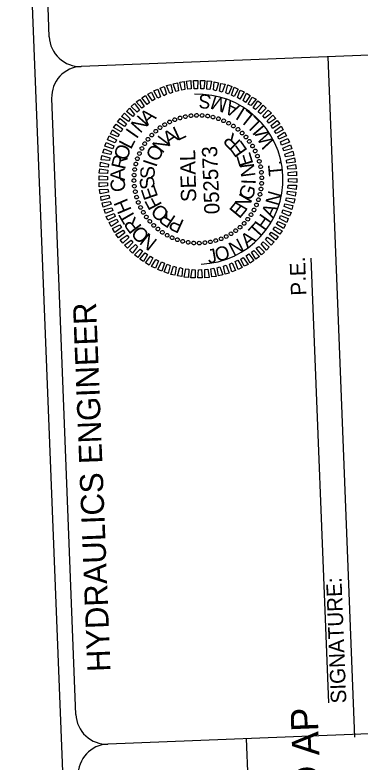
# Model space of a CAD drawing. Extents: x 1624323 to 1631382, y 753034 to 769560.
# Drawn here: x 1629687 to 1630364, y 765176 to 766642 of the extents above; entities that cross this region are included whole.
import ezdxf

# ---------------------------------------------------------------- set-up
doc = ezdxf.new("R2010")
doc.units = 0
for name, color, linetype in [('Old_Level_1', 7, 'Continuous'), ('Scratch_Level_0', 7, 'Continuous'), ('Sheet Data Field CELL', 7, 'Continuous'), ('Sheet Professional Seal CELL', 7, 'Continuous'), ('Sheet Profile Grid Minor CELL', 7, 'Continuous'), ('Sheet Title CELL', 7, 'Continuous')]:
    doc.layers.add(name, color=color, linetype=linetype)

msp = doc.modelspace()

# ---------------------------------------------------------------- linework, layer by layer
at = {"layer": 'Scratch_Level_0'}
msp.add_arc((1630045.7, 766319.7), 166.8, 272.2582, 92.2582, dxfattribs=at)
at = {"layer": 'Sheet Professional Seal CELL'}
for p, q in [((1630000.1, 766436.7), (1630000.1, 766436.7)), ((1630010.4, 766440.1), (1630010.4, 766440.1)), ((1630021.3, 766442.5), (1630021.3, 766442.5)), ((1630032, 766444.5), (1630032, 766444.5)), ((1630043, 766445.1), (1630043, 766445.1)), ((1630054, 766444.8), (1630054, 766444.8)), ((1630064.8, 766443.5), (1630064.8, 766443.5)), ((1630075.4, 766441.7), (1630075.4, 766441.7)), ((1630086.1, 766438.6), (1630086.1, 766438.6)), ((1630096.2, 766434.5), (1630096.2, 766434.5)), ((1629971.4, 766420.8), (1629971.4, 766420.8)), ((1629980.7, 766426.9), (1629980.7, 766426.9)), ((1629990.2, 766432.3), (1629990.2, 766432.3)), ((1630106.2, 766429.9), (1630106.2, 766429.9)), ((1630115.4, 766424), (1630115.4, 766424)), ((1629955, 766406.4), (1629955, 766406.4)), ((1629962.9, 766414.2), (1629962.9, 766414.2)), ((1630124.4, 766417.6), (1630124.4, 766417.6)), ((1630132.4, 766410.4), (1630132.4, 766410.4)), ((1629947.8, 766398.4), (1629947.8, 766398.4)), ((1630140.3, 766402.4), (1630140.3, 766402.4)), ((1630146.9, 766394), (1630146.9, 766394)), ((1629935.5, 766380.1), (1629935.5, 766380.1)), ((1629941.4, 766389.4), (1629941.4, 766389.4)), ((1630153, 766384.7), (1630153, 766384.7)), ((1630158.4, 766375.1), (1630158.4, 766375.1)), ((1629930.9, 766370.2), (1629930.9, 766370.2)), ((1630162.8, 766365.3), (1630162.8, 766365.3)), ((1629923.7, 766349.4), (1629923.7, 766349.4)), ((1629926.8, 766360), (1629926.8, 766360)), ((1630166.2, 766354.9), (1630166.2, 766354.9)), ((1629921.9, 766338.8), (1629921.9, 766338.8)), ((1630168.6, 766344), (1630168.6, 766344)), ((1630170.5, 766333.3), (1630170.5, 766333.3)), ((1629920.2, 766317), (1629920.2, 766317)), ((1629920.5, 766328), (1629920.5, 766328)), ((1630045.7, 766319.7), (1630045.7, 766319.7)), ((1630171.2, 766322.4), (1630171.2, 766322.4)), ((1629920.9, 766306), (1629920.9, 766306)), ((1630170.9, 766311.3), (1630170.9, 766311.3)), ((1629922.8, 766295.3), (1629922.8, 766295.3)), ((1630167.7, 766289.9), (1630167.7, 766289.9)), ((1630169.6, 766300.5), (1630169.6, 766300.5)), ((1629925.3, 766284.4), (1629925.3, 766284.4)), ((1629928.7, 766274), (1629928.7, 766274)), ((1630164.6, 766279.3), (1630164.6, 766279.3)), ((1629933.1, 766264.2), (1629933.1, 766264.2)), ((1630155.9, 766259.2), (1630155.9, 766259.2)), ((1630160.5, 766269.1), (1630160.5, 766269.1)), ((1629938.4, 766254.6), (1629938.4, 766254.6)), ((1629944.6, 766245.4), (1629944.6, 766245.4)), ((1630150, 766250), (1630150, 766250)), ((1629951.1, 766236.9), (1629951.1, 766236.9)), ((1629959, 766228.9), (1629959, 766228.9)), ((1630136.4, 766232.9), (1630136.4, 766232.9)), ((1630143.6, 766241), (1630143.6, 766241)), ((1629967, 766221.7), (1629967, 766221.7)), ((1629976, 766215.3), (1629976, 766215.3)), ((1630120, 766218.5), (1630120, 766218.5)), ((1630128.5, 766225.1), (1630128.5, 766225.1)), ((1629985.3, 766209.4), (1629985.3, 766209.4)), ((1629995.2, 766204.8), (1629995.2, 766204.8)), ((1630005.4, 766200.7), (1630005.4, 766200.7)), ((1630081, 766199.2), (1630081, 766199.2)), ((1630091.4, 766202.6), (1630091.4, 766202.6)), ((1630101.2, 766207), (1630101.2, 766207)), ((1630110.7, 766212.4), (1630110.7, 766212.4)), ((1630016, 766197.6), (1630016, 766197.6)), ((1630026.6, 766195.8), (1630026.6, 766195.8)), ((1630037.4, 766194.5), (1630037.4, 766194.5)), ((1630048.4, 766194.2), (1630048.4, 766194.2)), ((1630059.4, 766194.8), (1630059.4, 766194.8)), ((1630070.1, 766196.8), (1630070.1, 766196.8))]:
    msp.add_line(p, q, dxfattribs=at)
for points in [[(1630002.4, 766491.6), (1629997, 766507.1), (1630005.5, 766509), (1630007.6, 766493.3)], [(1630014.3, 766494.3), (1630010.2, 766510.4), (1630018.6, 766511.5), (1630020.3, 766495.5)], [(1630026.2, 766496.3), (1630023.6, 766512.4), (1630032.1, 766513.3), (1630032.2, 766497)], [(1630038.7, 766497), (1630037.3, 766513.2), (1630045.8, 766513.6), (1630044.7, 766497.3)], [(1630051.2, 766497.3), (1630051.1, 766513.5), (1630059.3, 766513.3), (1630057.2, 766497)], [(1630063.3, 766496.5), (1630064.1, 766512.5), (1630072.7, 766511.9), (1630069.3, 766495.5)], [(1630076.1, 766495), (1630077.5, 766510.6), (1630086, 766509.1), (1630081.4, 766493.2)], [(1630088.2, 766492.2), (1630090.8, 766507.8), (1630099.1, 766506.4), (1630093.5, 766490.4)], [(1629967.1, 766478.7), (1629959.1, 766493.1), (1629966.9, 766496.7), (1629972.5, 766481.4)], [(1629978.7, 766483.6), (1629971.6, 766498.6), (1629979.2, 766501.7), (1629983.8, 766486.3)], [(1629990.5, 766488.1), (1629984.2, 766503.9), (1629992.3, 766505.7), (1629995.7, 766490.1)], [(1630100.3, 766488.9), (1630104.2, 766504.6), (1630112.1, 766501.7), (1630105.7, 766486.4)], [(1630111.5, 766484.4), (1630116.7, 766500.1), (1630124.5, 766496.7), (1630117.1, 766482.1)], [(1630123.2, 766479.8), (1630128.9, 766494.3), (1630136.8, 766490.9), (1630128.1, 766477)], [(1629945.9, 766466.3), (1629935.8, 766479.2), (1629943.1, 766484.2), (1629950.7, 766470)], [(1629956.6, 766473.3), (1629947.3, 766486.9), (1629954.9, 766490.5), (1629961.2, 766476.5)], [(1630134.2, 766474.3), (1630141.1, 766488.5), (1630148.3, 766483.8), (1630138.8, 766470.4)], [(1630144.5, 766467.2), (1630152.4, 766481), (1630159.9, 766476.5), (1630149.3, 766464.1)], [(1629926.4, 766451.6), (1629914.7, 766462.6), (1629921.3, 766468.1), (1629931.3, 766455.3)], [(1629935.9, 766459.4), (1629924.9, 766471.3), (1629931.9, 766476.3), (1629940.5, 766462.6)], [(1630154.3, 766460), (1630163.5, 766473.4), (1630170.2, 766468.2), (1630158.9, 766456.7)], [(1630164.1, 766451.7), (1630173.8, 766464.8), (1630179.8, 766458.8), (1630168.3, 766447.8)], [(1629909.4, 766433.1), (1629896, 766442.9), (1629901.7, 766449.1), (1629912.9, 766438)], [(1629917.8, 766442.5), (1629905.6, 766452.7), (1629911.4, 766459), (1629921.6, 766446.4)], [(1630173.2, 766443.8), (1630183.7, 766455.2), (1630190, 766449.4), (1630176.9, 766439.2)], [(1629902, 766423.3), (1629887.9, 766432), (1629893.1, 766438.7), (1629905.3, 766428.2)], [(1630181.3, 766434.1), (1630192.9, 766445.3), (1630198.4, 766438.8), (1630184.7, 766429.5)], [(1630189.2, 766424.9), (1630201.5, 766434.6), (1630206.6, 766428.3), (1630192.4, 766419.5)], [(1629894.9, 766412.8), (1629880.1, 766421), (1629885.1, 766427.7), (1629897.7, 766418.4)], [(1630195.9, 766414.1), (1630209, 766423.9), (1630213.3, 766416.3), (1630199, 766409.5)], [(1629883.3, 766391.1), (1629868.3, 766396.7), (1629871.5, 766404.6), (1629885.8, 766396.7)], [(1629888.6, 766402.8), (1629874.1, 766409), (1629878, 766416.6), (1629891.4, 766407.6)], [(1630202.3, 766403.6), (1630215.9, 766412.2), (1630219.7, 766404.6), (1630204.7, 766398.2)], [(1629879, 766379.6), (1629863, 766384.8), (1629865.7, 766391.9), (1629880.5, 766385.4)], [(1630207.9, 766392.9), (1630222.2, 766399.9), (1630225.5, 766392.5), (1630209.7, 766386.7)], [(1629874.9, 766368.2), (1629859.3, 766371.4), (1629861.5, 766379.2), (1629876.5, 766373.5)], [(1630212.4, 766380.8), (1630227.2, 766387.1), (1630229.7, 766379.5), (1630214.4, 766375.6)], [(1629872.1, 766356.1), (1629855.8, 766358), (1629857.5, 766366.5), (1629873.2, 766361.4)], [(1630216.1, 766368.9), (1630231.7, 766374.8), (1630233.8, 766366.4), (1630217.6, 766363.7)], [(1630219.4, 766357), (1630235.2, 766361.7), (1630236.3, 766353.4), (1630220.4, 766351.1)], [(1629869.9, 766343.2), (1629853.8, 766344.9), (1629854.7, 766353.2), (1629870.4, 766349.3)], [(1630221.3, 766345.1), (1630237.2, 766348.5), (1630238.6, 766340), (1630222.3, 766339.1)], [(1629868.4, 766331.2), (1629852.1, 766331.5), (1629853.3, 766339.8), (1629869.1, 766337.2)], [(1630223.1, 766332.7), (1630239.3, 766334.5), (1630239.3, 766326.3), (1630223.1, 766326.7)], [(1629868.1, 766318.7), (1629851.9, 766318), (1629851.8, 766326.3), (1629868.1, 766324.7)], [(1630223.3, 766320.7), (1630239.5, 766321.3), (1630239.6, 766313), (1630223.3, 766314.7)], [(1629868.3, 766306.7), (1629852.1, 766304.8), (1629852.1, 766313), (1629868.3, 766312.7)], [(1630223, 766308.1), (1630239.3, 766307.8), (1630238.2, 766299.5), (1630222.3, 766302.1)], [(1629870.1, 766294.2), (1629854.2, 766290.8), (1629852.9, 766299.3), (1629869.1, 766300.2)], [(1629872, 766282.3), (1629856.2, 766277.7), (1629855.1, 766285.9), (1629871.1, 766288.3)], [(1630221.5, 766296.1), (1630237.6, 766294.4), (1630236.7, 766286.2), (1630221, 766290)], [(1629875.3, 766270.4), (1629859.7, 766264.5), (1629857.7, 766273), (1629873.8, 766275.6)], [(1630219.3, 766283.2), (1630235.6, 766281.4), (1630234, 766272.8), (1630218.2, 766277.9)], [(1629879, 766258.5), (1629864.2, 766252.2), (1629861.7, 766259.9), (1629877, 766263.7)], [(1630212.5, 766259.7), (1630228.4, 766254.6), (1630225.7, 766247.4), (1630210.9, 766253.9)], [(1630216.5, 766271.1), (1630232.1, 766268), (1630229.9, 766260.1), (1630215, 766265.8)], [(1629883.5, 766246.5), (1629869.2, 766239.4), (1629865.9, 766246.8), (1629881.7, 766252.6)], [(1630208.1, 766248.3), (1630223.1, 766242.6), (1630219.9, 766234.7), (1630205.6, 766242.6)], [(1629889.1, 766235.7), (1629875.5, 766227.1), (1629871.7, 766234.7), (1629886.7, 766241.1)], [(1629895.6, 766225.2), (1629882.4, 766215.4), (1629878.1, 766223), (1629892.4, 766229.8)], [(1630202.9, 766236.5), (1630217.4, 766230.4), (1630213.4, 766222.7), (1630200, 766231.7)], [(1629902.2, 766214.4), (1629889.9, 766204.7), (1629884.9, 766211), (1629899, 766219.8)], [(1630189.4, 766216), (1630203.5, 766207.3), (1630198.3, 766200.6), (1630186.1, 766211.1)], [(1630196.5, 766226.5), (1630211.3, 766218.4), (1630206.3, 766211.7), (1630193.7, 766220.9)], [(1629910.1, 766205.2), (1629898.5, 766194), (1629893, 766200.5), (1629906.7, 766209.8)], [(1629918.2, 766195.5), (1629907.7, 766184.1), (1629901.5, 766189.9), (1629914.6, 766200.1)], [(1630182, 766206.2), (1630195.4, 766196.5), (1630189.7, 766190.2), (1630178.5, 766201.3)], [(1629927.3, 766187.6), (1629917.6, 766174.5), (1629911.6, 766180.5), (1629923.2, 766191.5)], [(1630165, 766187.8), (1630176.7, 766176.7), (1630170.2, 766171.2), (1630160.1, 766184.1)], [(1630173.6, 766196.9), (1630185.8, 766186.6), (1630180.1, 766180.3), (1630169.8, 766192.9)], [(1629937.2, 766179.3), (1629927.9, 766165.9), (1629921.2, 766171.1), (1629932.5, 766182.6)], [(1629946.9, 766172.2), (1629939, 766158.3), (1629931.6, 766162.8), (1629942.1, 766175.2)], [(1630145.6, 766173), (1630155.6, 766160.1), (1630148.3, 766155.1), (1630140.7, 766169.3)], [(1630155.6, 766179.9), (1630166.5, 766168.1), (1630159.5, 766163), (1630150.9, 766176.7)], [(1629957.2, 766165.1), (1629950.3, 766150.8), (1629943.1, 766155.5), (1629952.6, 766168.9)], [(1629968.2, 766159.5), (1629962.5, 766145), (1629954.6, 766148.4), (1629963.3, 766162.3)], [(1629979.9, 766154.9), (1629974.8, 766139.2), (1629966.9, 766142.7), (1629974.3, 766157.2)], [(1630112.7, 766155.7), (1630119.8, 766140.7), (1630112.2, 766137.6), (1630107.6, 766153)], [(1630124.3, 766160.6), (1630132.4, 766146.2), (1630124.5, 766142.6), (1630118.9, 766157.9)], [(1630134.8, 766166), (1630144.1, 766152.4), (1630136.5, 766148.9), (1630130.2, 766162.9)], [(1629991.1, 766150.4), (1629987.2, 766134.7), (1629979.3, 766137.7), (1629985.7, 766152.9)], [(1630003.2, 766147.1), (1630000.6, 766131.5), (1629992.3, 766132.9), (1629997.9, 766148.9)], [(1630015.3, 766144.3), (1630014, 766128.8), (1630005.4, 766130.2), (1630010, 766146.1)], [(1630028.2, 766142.8), (1630027.3, 766126.8), (1630018.8, 766127.4), (1630022.1, 766143.8)], [(1630040.2, 766142.1), (1630040.3, 766125.8), (1630032.1, 766126), (1630034.2, 766142.3)], [(1630052.7, 766142.3), (1630054.1, 766126.1), (1630045.6, 766125.8), (1630046.7, 766142.1)], [(1630065.2, 766143), (1630067.8, 766126.9), (1630059.3, 766126), (1630059.2, 766142.3)], [(1630077.1, 766145), (1630081.3, 766128.9), (1630072.8, 766127.8), (1630071.2, 766143.8)], [(1630089, 766147.7), (1630094.4, 766132.2), (1630085.9, 766130.3), (1630083.8, 766146)], [(1630100.9, 766151.2), (1630107.3, 766135.4), (1630099.1, 766133.6), (1630095.7, 766149.2)]]:
    msp.add_lwpolyline(points, close=True, dxfattribs=at)
for centre, major_axis in [((1630043, 766445), (-0.08, 3.6)), ((1630053.9, 766444.8), (0.23, 3.59)), ((1629990.2, 766432.1), (-1.59, 3.23)), ((1630000.2, 766436.5), (-1.31, 3.36)), ((1630010.6, 766440), (-1.01, 3.46)), ((1630021.2, 766442.6), (-0.7, 3.53)), ((1630032, 766444.3), (-0.39, 3.58)), ((1630064.8, 766443.6), (0.55, 3.56)), ((1630075.5, 766441.5), (0.86, 3.5)), ((1630086, 766438.4), (1.16, 3.41)), ((1630096.2, 766434.4), (1.45, 3.3)), ((1629971.5, 766420.8), (-2.13, 2.9)), ((1629980.6, 766426.9), (-1.87, 3.08)), ((1630106, 766429.6), (1.73, 3.16)), ((1630115.4, 766423.9), (2, 2.99)), ((1630124.2, 766417.5), (2.25, 2.81)), ((1629955.1, 766406.4), (-2.6, 2.49)), ((1629963, 766413.9), (-2.37, 2.71)), ((1630132.4, 766410.3), (2.49, 2.6)), ((1630140, 766402.4), (2.71, 2.37)), ((1629941.4, 766389.3), (-2.99, 2)), ((1629947.9, 766398.1), (-2.81, 2.25)), ((1630146.8, 766393.8), (2.9, 2.13)), ((1629935.8, 766380), (-3.16, 1.73)), ((1630152.9, 766384.7), (3.08, 1.87)), ((1630158.2, 766375.1), (3.23, 1.59)), ((1629927, 766359.9), (-3.41, 1.16)), ((1629930.9, 766370.1), (-3.3, 1.45)), ((1630162.6, 766365.1), (3.36, 1.31)), ((1629923.9, 766349.4), (-3.5, 0.86)), ((1630166.1, 766354.8), (3.46, 1.01)), ((1630168.7, 766344.1), (3.53, 0.7)), ((1629920.6, 766327.8), (-3.59, 0.23)), ((1629921.8, 766338.7), (-3.56, 0.55)), ((1630170.4, 766333.3), (3.58, 0.39)), ((1629920.3, 766316.9), (-3.6, -0.08)), ((1630171.1, 766322.4), (3.6, 0.08)), ((1629921.1, 766306), (-3.58, -0.39)), ((1630169.7, 766300.6), (3.56, -0.55)), ((1630170.8, 766311.5), (3.59, -0.23)), ((1629922.7, 766295.2), (-3.53, -0.7)), ((1629925.3, 766284.5), (-3.46, -1.01)), ((1630167.5, 766289.9), (3.5, -0.86)), ((1629928.8, 766274.2), (-3.36, -1.31)), ((1630160.5, 766269.2), (3.3, -1.45)), ((1630164.5, 766279.4), (3.41, -1.16)), ((1629933.2, 766264.2), (-3.23, -1.59)), ((1629938.5, 766254.6), (-3.08, -1.87)), ((1630155.7, 766259.4), (3.16, -1.73)), ((1629944.6, 766245.5), (-2.9, -2.13)), ((1630143.5, 766241.2), (2.81, -2.25)), ((1630150, 766250), (2.99, -2)), ((1629951.4, 766237), (-2.71, -2.37)), ((1629959, 766229.1), (-2.49, -2.6)), ((1630128.4, 766225.4), (2.37, -2.71)), ((1630136.3, 766233), (2.6, -2.49)), ((1629967.2, 766221.8), (-2.25, -2.81)), ((1629976.1, 766215.4), (-2, -2.99)), ((1629985.4, 766209.7), (-1.73, -3.16)), ((1630110.8, 766212.5), (1.87, -3.08)), ((1630119.9, 766218.5), (2.13, -2.9)), ((1629995.2, 766204.9), (-1.45, -3.3)), ((1630005.4, 766200.9), (-1.16, -3.41)), ((1630015.9, 766197.8), (-0.86, -3.5)), ((1630026.6, 766195.7), (-0.55, -3.56)), ((1630070.2, 766196.7), (0.7, -3.53)), ((1630080.8, 766199.3), (1.01, -3.46)), ((1630091.2, 766202.8), (1.31, -3.36)), ((1630101.2, 766207.2), (1.59, -3.23)), ((1630037.5, 766194.5), (-0.23, -3.59)), ((1630048.5, 766194.3), (0.08, -3.6)), ((1630059.4, 766195), (0.39, -3.58))]:
    msp.add_ellipse(centre, major_axis=major_axis, ratio=0.999708, dxfattribs=at)
at = {"layer": 'Sheet Title CELL'}
for p, q in [((1630025.6, 758943.2), (1629686.7, 767537.4)), ((1629754, 766599.1), (1629717, 767538.6)), ((1630785.3, 766579.2), (1629817, 766541)), ((1630353.7, 765224.5), (1630301, 766560.1)), ((1629806.5, 765269), (1629758.8, 766478.1)), ((1630302.6, 765291.6), (1630268.2, 766164.6)), ((1630837.9, 765249.1), (1629869.5, 765210.9)), ((1630140.3, 765221.6), (1630213, 763375.6))]:
    msp.add_line(p, q, dxfattribs=at)
for centre, start, end in [((1629814.6, 766601.5), 182.2582, 272.2582), ((1629819.3, 766480.5), 92.2582, 182.2582), ((1629866.8, 765271.4), 182.2582, 272.2582), ((1629871.5, 765150.4), 92.2582, 182.2582)]:
    msp.add_arc(centre, 60.6, start, end, dxfattribs=at)

# ---------------------------------------------------------------- texts
at = {"layer": 'Old_Level_1'}
for s, rotation, p in [('S', 173.4464, (1630073.2, 766484.4)), ('M', 161.826, (1630105.8, 766475.5)), ('A', 152.6957, (1630129.8, 766464)), ('I', 148.2307, (1630140.7, 766457)), ('L', 141.476, (1630156.2, 766444.9)), ('L', 134.7213, (1630170.2, 766431)), ('I', 130.2563, (1630178.5, 766421)), ('W', 117.7057, (1630197.3, 766389.7)), ('T', 95.3951, (1630212.6, 766326.9)), ('.', 102.6364, (1630210.3, 766347.9)), ('N', 74.1292, (1630203.9, 766265.9)), ('A', 64.9989, (1630193.3, 766241.5)), ('H', 54.8096, (1630177.2, 766216.6)), ('T', 47.5683, (1630163.1, 766200.9)), ('A', 38.438, (1630142.8, 766183.7)), ('N', 27.5618, (1630115.4, 766167.9)), ('O', 15.9128, (1630083.3, 766156.9)), ('J', 10.0997, (1630066.6, 766153.9))]:
    msp.add_text(s, height=27.5, rotation=rotation, dxfattribs=at).set_placement(p)
at = {"layer": 'Sheet Data Field CELL'}
msp.add_text('RAJIT RAMKUMAR, PE, LEED AP', height=52.999, rotation=92.2582, dxfattribs=at).set_placement((1630323.7, 764181.8))
at = {"layer": 'Sheet Professional Seal CELL'}
for s, height, rotation, p in [('A', 28.2, 40.8753, (1629946.8, 766423.8)), ('N', 28.2, 48.0771, (1629932.6, 766408.5)), ('I', 28.2, 55.2783, (1629925.3, 766397.5)), ('L', 28.2, 24.659, (1630005.5, 766394.4)), ('N', 28.2, 52.7348, (1629976.2, 766369.2)), ('A', 28.2, 34.0185, (1629988.6, 766384)), ('R', 28.2, 134.7396, (1630131.6, 766393.6)), ('L', 28.2, 62.4791, (1629914.1, 766376.8)), ('E', 28.2, 125.3823, (1630144.1, 766376.3)), ('O', 28.2, 69.6794, (1629905.7, 766354.4)), ('O', 28.2, 62.0917, (1629966.9, 766352.1)), ('SEAL', 29.99, 91.2582, (1630042.5, 766275.2)), ('R', 28.2, 76.8793, (1629902.6, 766337.5)), ('E', 28.2, 106.67, (1630154.8, 766350.2)), ('I', 28.2, 71.4478, (1629963.8, 766341.9)), ('N', 28.2, 97.3146, (1630158.8, 766325.6)), ('A', 28.2, 91.2785, (1629902.5, 766316.5)), ('S', 28.2, 90.1586, (1629961.1, 766320.3)), ('C', 28.2, 98.4781, (1629904.7, 766296.8)), ('S', 28.2, 99.5138, (1629962.1, 766302.3)), ('I', 28.2, 87.9594, (1630158.7, 766308.9)), ('E', 28.2, 108.8693, (1629968, 766285.3)), ('G', 28.2, 69.2484, (1630150.5, 766275.8)), ('N', 28.2, 59.8921, (1630140, 766256.3)), ('H', 28.2, 112.8777, (1629916.2, 766259.3)), ('F', 28.2, 118.2252, (1629976.1, 766269.6)), ('E', 28.2, 50.5351, (1630127.1, 766240.8)), ('O', 28.2, 136.9394, (1629991.5, 766253.7)), ('R', 28.2, 146.2978, (1630004.1, 766245.5)), ('T', 28.2, 120.078, (1629925.1, 766243.3)), ('R', 28.2, 127.2787, (1629936.8, 766226.8)), ('P', 28.2, 155.6571, (1630020.4, 766238.1)), ('O', 28.2, 134.4799, (1629952.9, 766210.2)), ('N', 28.2, 141.6817, (1629967.9, 766199.2))]:
    msp.add_text(s, height=height, rotation=rotation, dxfattribs=at).set_placement(p)
at = {"layer": 'Sheet Profile Grid Minor CELL'}
msp.add_text('052573', height=29.99, rotation=92.2582, dxfattribs=at).set_placement((1630088.5, 766251.5))
at = {"layer": 'Sheet Title CELL'}
for s, height, p in [('P.E.', 30.28, (1630258.7, 766091.8)), (' HYDRAULICS ENGINEER', 45.428, (1629875.1, 765336.6)), ('SIGNATURE:', 30.28, (1630337.1, 765291.3))]:
    msp.add_text(s, height=height, rotation=92.2582, dxfattribs=at).set_placement(p)

doc.saveas('drawing.dxf')
